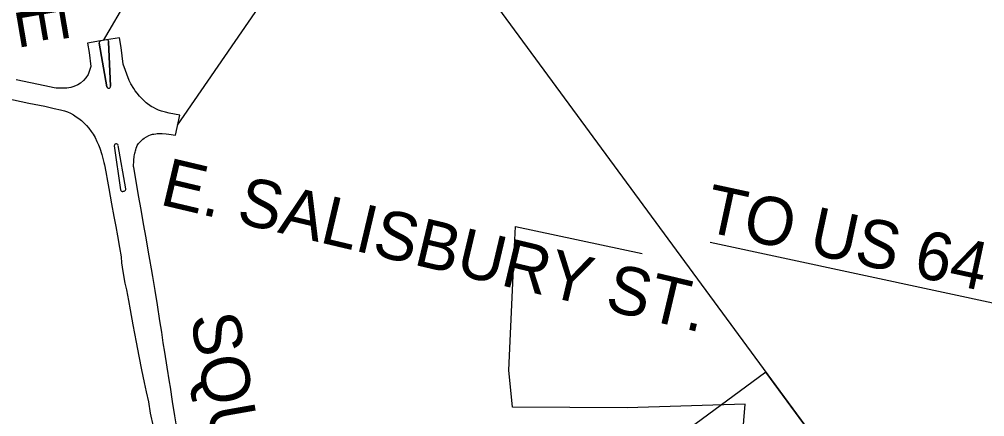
# Model space of a CAD drawing. Extents: x 1754939 to 1770240, y 706534 to 717510.
# Drawn here: x 1763770 to 1764774, y 712091 to 712504 of the extents above; entities that cross this region are included whole.
import ezdxf

# ---------------------------------------------------------------- set-up
doc = ezdxf.new("R2010")
doc.units = 0
for name, color, linetype in [('ENG SEALS CELL', 7, 'Continuous'), ('Prop Conc Curb 8in x 6in', 7, 'Continuous'), ('Prop Lane Arrow CELL', 7, 'Continuous'), ('Prop SS Cut Line', 7, 'Continuous'), ('Sheet PE Seal Cell', 7, 'Continuous')]:
    doc.layers.add(name, color=color, linetype=linetype)

msp = doc.modelspace()

# ---------------------------------------------------------------- linework, layer by layer
at = {"layer": 'ENG SEALS CELL'}
for points in [[(1763819.2, 711353.8), (1763256.7, 712119.2), (1763567.1, 712347.6), (1763674.3, 712850.2), (1763900.7, 713016.1), (1764665.2, 711975.8), (1764374.3, 711762)], [(1764665.2, 711975.8), (1764546.7, 712137), (1764406.8, 712034.2), (1764525.3, 711873)]]:
    msp.add_lwpolyline(points, close=True, dxfattribs=at)
at = {"layer": 'Prop Conc Curb 8in x 6in'}
for p, q in [((1763853.2, 712479.4), (1763861.2, 712434.1)), ((1763860.8, 712482.7), (1763854.8, 712481.7)), ((1763865.1, 712434.6), (1763863.1, 712480.8)), ((1763869, 712372.5), (1763875.5, 712326.9)), ((1763881, 712327.8), (1763873, 712373.1)), ((1763877.9, 712325.3), (1763879.4, 712325.5))]:
    msp.add_line(p, q, dxfattribs=at)
for centre, start, end in [((1763855.2, 712479.8), 99.4894, 190.0204), ((1763861.2, 712480.8), 2.4741, 99.4894), ((1763863.2, 712434.5), 190.0204, 2.4741), ((1763871, 712372.8), 100.0204, 188.1527), ((1763871, 712372.8), 10.0204, 100.0204), ((1763877.5, 712327.2), 188.1527, 280.0204), ((1763879, 712327.5), 280.0204, 10.0204)]:
    msp.add_arc(centre, 2, start, end, dxfattribs=at)
at = {"layer": 'Prop Lane Arrow CELL'}
for p, q in [((1763854.8, 712481.7), (1763841.2, 712479.5)), ((1763841.2, 712479.5), (1763842.9, 712469.6)), ((1763861.2, 712434.1), (1763853.2, 712479.4)), ((1763874.5, 712485), (1763860.8, 712482.7)), ((1763863.1, 712480.8), (1763865.1, 712434.6)), ((1763876.2, 712475), (1763874.5, 712485)), ((1763842.9, 712469.6), (1763844.6, 712455)), ((1763878.3, 712457.4), (1763876.2, 712475)), ((1763884.5, 712440.4), (1763878.3, 712457.4)), ((1763844.6, 712455), (1763841.8, 712446.8)), ((1763796.6, 712435.1), (1763767.1, 712441.3)), ((1763834, 712437.9), (1763831.1, 712436.2)), ((1763837, 712440.6), (1763834, 712437.9)), ((1763839.4, 712443.2), (1763837, 712440.6)), ((1763841.8, 712446.8), (1763839.4, 712443.2)), ((1763886.1, 712437.2), (1763884.5, 712440.4)), ((1763889.2, 712432.1), (1763886.1, 712437.2)), ((1763806.6, 712433.1), (1763796.6, 712435.1)), ((1763808.7, 712432.7), (1763806.6, 712433.1)), ((1763815.5, 712432.6), (1763808.7, 712432.7)), ((1763819.7, 712432.5), (1763815.5, 712432.6)), ((1763823.8, 712433.3), (1763819.7, 712432.5)), ((1763827, 712434.3), (1763823.8, 712433.3)), ((1763831.1, 712436.2), (1763827, 712434.3)), ((1763890.8, 712429.9), (1763889.2, 712432.1)), ((1763892.7, 712427.4), (1763890.8, 712429.9)), ((1763895.3, 712424.3), (1763892.7, 712427.4)), ((1763756.2, 712422.2), (1763780, 712417)), ((1763780, 712417), (1763796.6, 712413.7)), ((1763899.5, 712420), (1763895.3, 712424.3)), ((1763902.3, 712417.3), (1763899.5, 712420)), ((1763907.5, 712413.6), (1763902.3, 712417.3)), ((1763796.6, 712413.7), (1763806.3, 712411.6)), ((1763806.3, 712411.6), (1763813.1, 712410.2)), ((1763813.1, 712410.2), (1763817.2, 712409)), ((1763817.2, 712409), (1763820.4, 712407.9)), ((1763820.4, 712407.9), (1763823.5, 712406.6)), ((1763909.8, 712412.3), (1763907.5, 712413.6)), ((1763912.1, 712411.2), (1763909.8, 712412.3)), ((1763915, 712409.8), (1763912.1, 712411.2)), ((1763916.9, 712409.1), (1763915, 712409.8)), ((1763918.2, 712408.6), (1763916.9, 712409.1)), ((1763922.4, 712407.5), (1763918.2, 712408.6)), ((1763925.9, 712406.7), (1763922.4, 712407.5)), ((1763823.5, 712406.6), (1763826.5, 712404.9)), ((1763826.5, 712404.9), (1763829.5, 712402.9)), ((1763829.5, 712402.9), (1763832.2, 712401)), ((1763832.2, 712401), (1763834.8, 712398.8)), ((1763834.8, 712398.8), (1763837.8, 712396)), ((1763937, 712404.4), (1763925.9, 712406.7)), ((1763932.7, 712383.8), (1763937, 712404.4)), ((1763837.8, 712396), (1763840.2, 712393.6)), ((1763840.2, 712393.6), (1763842.4, 712390.8)), ((1763842.4, 712390.8), (1763845, 712387.4)), ((1763845, 712387.4), (1763846.9, 712384.6)), ((1763846.9, 712384.6), (1763849, 712381.2)), ((1763849, 712381.2), (1763851, 712377.1)), ((1763851, 712377.1), (1763852.5, 712373.6)), ((1763894.3, 712375.1), (1763898.7, 712379.5)), ((1763898.7, 712379.5), (1763899.9, 712380.5)), ((1763899.9, 712380.5), (1763904.8, 712383.5)), ((1763904.8, 712383.5), (1763906.8, 712384.1)), ((1763906.8, 712384.1), (1763908.8, 712384.6)), ((1763908.8, 712384.6), (1763910.1, 712384.8)), ((1763910.1, 712384.8), (1763912.1, 712385.2)), ((1763912.1, 712385.2), (1763913.7, 712385.3)), ((1763913.7, 712385.3), (1763918.8, 712385.3)), ((1763918.8, 712385.3), (1763922.8, 712385.1)), ((1763922.8, 712385.1), (1763925.8, 712384.8)), ((1763925.8, 712384.8), (1763932.7, 712383.8)), ((1763852.5, 712373.6), (1763853.9, 712370.2)), ((1763853.9, 712370.2), (1763856, 712363.7)), ((1763890.6, 712366.1), (1763890.9, 712367.3)), ((1763890.9, 712367.3), (1763891.4, 712368.6)), ((1763891.4, 712368.6), (1763891.9, 712370.3)), ((1763891.9, 712370.3), (1763892.4, 712371.8)), ((1763892.4, 712371.8), (1763892.9, 712372.8)), ((1763892.9, 712372.8), (1763893.6, 712374)), ((1763893.6, 712374), (1763894.3, 712375.1)), ((1763856, 712363.7), (1763858.1, 712355.3)), ((1763889.1, 712351.1), (1763889.3, 712357.2)), ((1763889.3, 712357.2), (1763889.8, 712361.7)), ((1763889.8, 712361.7), (1763890.1, 712363.3)), ((1763890.1, 712363.3), (1763890.3, 712364.9)), ((1763890.3, 712364.9), (1763890.6, 712366.1)), ((1763858.1, 712355.3), (1763858.8, 712352.7)), ((1763858.8, 712352.7), (1763860.2, 712345.4)), ((1763889.2, 712350.2), (1763889.1, 712351.1)), ((1763891.6, 712335.9), (1763889.2, 712350.2)), ((1763860.2, 712345.4), (1763862, 712335.8)), ((1763862, 712335.8), (1763863.4, 712328.1)), ((1763863.4, 712328.1), (1763864.7, 712320.1)), ((1763894.2, 712321), (1763891.6, 712335.9)), ((1763864.7, 712320.1), (1763866.2, 712312.1)), ((1763897, 712306.3), (1763894.2, 712321)), ((1763866.2, 712312.1), (1763868.6, 712299)), ((1763868.6, 712299), (1763870.5, 712288.6)), ((1763899.4, 712291.5), (1763897, 712306.3)), ((1763870.5, 712288.6), (1763872.3, 712278.8)), ((1763902, 712276.8), (1763899.4, 712291.5)), ((1763872.3, 712278.8), (1763874.5, 712266.7)), ((1763904.5, 712262), (1763902, 712276.8)), ((1763874.5, 712266.7), (1763876.2, 712257.2)), ((1763876.2, 712257.2), (1763876.5, 712250.8)), ((1763906, 712254.2), (1763904.5, 712262)), ((1763876.5, 712250.8), (1763877.9, 712241.9)), ((1763907.7, 712244.6), (1763906, 712254.2)), ((1763877.9, 712241.9), (1763880.1, 712229.7)), ((1763909, 712236.8), (1763907.7, 712244.6)), ((1763911.4, 712222), (1763909, 712236.8)), ((1763880.1, 712229.7), (1763881.6, 712222.7)), ((1763881.6, 712222.7), (1763883.6, 712211.8)), ((1763913.9, 712207.2), (1763911.4, 712222)), ((1763883.6, 712211.8), (1763885.4, 712202.1)), ((1763916.5, 712190.6), (1763913.9, 712207.2)), ((1763885.4, 712202.1), (1763888.3, 712186.2)), ((1763888.3, 712186.2), (1763891.6, 712168.4)), ((1763918.5, 712178.6), (1763916.5, 712190.6)), ((1763920, 712167.6), (1763918.5, 712178.6)), ((1763891.6, 712168.4), (1763894.4, 712153.7)), ((1763921.5, 712158.1), (1763920, 712167.6)), ((1763924, 712142.3), (1763921.5, 712158.1)), ((1763894.4, 712153.7), (1763897.4, 712139.6)), ((1763897.4, 712139.6), (1763900, 712126.3)), ((1763926.4, 712127.2), (1763924, 712142.3)), ((1763900, 712126.3), (1763902.1, 712116.5)), ((1763927.3, 712121.4), (1763926.4, 712127.2)), ((1763902.1, 712116.5), (1763904.5, 712106.1)), ((1763929.7, 712106.6), (1763927.3, 712121.4)), ((1763904.5, 712106.1), (1763906.4, 712094.3)), ((1763932.1, 712091.8), (1763929.7, 712106.6)), ((1763906.4, 712094.3), (1763909.3, 712080.7)), ((1763934.4, 712077), (1763932.1, 712091.8))]:
    msp.add_line(p, q, dxfattribs=at)
for centre, start, end in [((1763855.2, 712479.8), 99.4894, 190.0204), ((1763861.2, 712480.8), 2.4741, 99.4894), ((1763863.2, 712434.5), 190.0204, 2.4741)]:
    msp.add_arc(centre, 2, start, end, dxfattribs=at)
at = {"layer": 'Prop SS Cut Line'}
for p, q in [((1763857.8, 712482.2), (1764356.1, 713338.2)), ((1763934.8, 712394.1), (1764371.1, 713029.5))]:
    msp.add_line(p, q, dxfattribs=at)
at = {"layer": 'Sheet PE Seal Cell'}
msp.add_line((1764934, 712176.2), (1764488.8, 712271.9), dxfattribs=at)
msp.add_lwpolyline([(1764519.9, 712039.9), (1764525.2, 712104), (1764402.5, 712100), (1764283.1, 712100.7), (1764279.4, 712139.2), (1764285.2, 712267.7), (1764286.4, 712288.5), (1764418.1, 712260.6)], dxfattribs=at)

# ---------------------------------------------------------------- texts
for s, rotation, p in [('COLERIDGE ', 279.6489, (1763707.3, 712860.6)), ('E. SALISBURY ST.', 346.6818, (1763915, 712311.8)), ('TO US 64', 347.8638, (1764480.7, 712284.1)), ('SQUARE ROAD', 280.0243, (1763948, 712194.9))]:
    msp.add_text(s, height=50, rotation=rotation, dxfattribs=at).set_placement(p)

doc.saveas('drawing.dxf')
